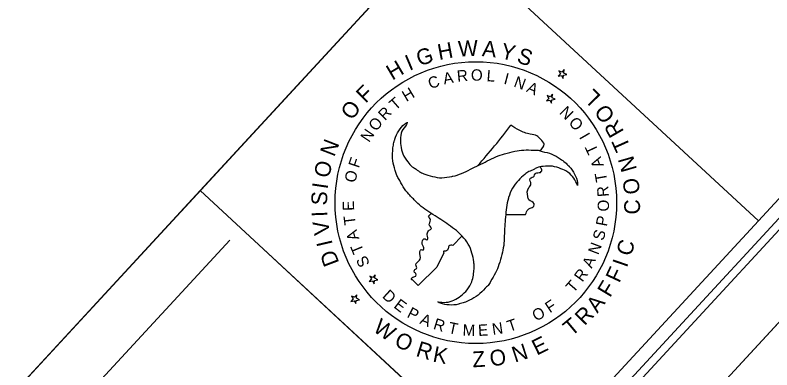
# Model space of a CAD drawing. Extents: x 1767460 to 1770129, y 996106 to 1001438.
# Drawn here: x 1769606.3 to 1769898.5, y 1000271.5 to 1000408.3 of the extents above; entities that cross this region are included whole.
import ezdxf

# ---------------------------------------------------------------- set-up
doc = ezdxf.new("R2010")
doc.units = 0
for name, color, linetype in [('E_NCDOT_Terrain_Model_Contour_Minor', 7, 'Continuous'), ('E_NCDOT_Terrain_Model_Points_Low', 7, 'Continuous'), ('E_NCDOT_Terrain_Model_Triangle_Vertices', 7, 'Continuous'), ('P_NCDOT_Terrain_Points_High', 7, 'Continuous'), ('P_RDY_TL_Draft_DNC_Null_Point', 7, 'Continuous'), ('P_RDY_TL_Grass_Shoulder_Normal', 7, 'Continuous')]:
    doc.layers.add(name, color=color, linetype=linetype)

msp = doc.modelspace()

# ---------------------------------------------------------------- linework, layer by layer
at = {"layer": 'E_NCDOT_Terrain_Model_Contour_Minor'}
msp.add_lwpolyline([(1768744.05, 999038.07), (1770128.77, 1000536.12), (1769152.55, 1001438.49), (1767767.83, 999940.44)], close=True, dxfattribs=at)
at = {"layer": 'E_NCDOT_Terrain_Model_Points_Low'}
msp.add_lwpolyline([(1767804.38, 999935.46), (1769171.05, 1001413.98), (1770107.33, 1000548.53), (1768740.66, 999070.01)], close=True, dxfattribs=at)
at = {"layer": 'E_NCDOT_Terrain_Model_Triangle_Vertices'}
for p, q in [((1769569.13, 1000191.69), (1769689.18, 1000321.56)), ((1769698.57, 1000321.36), (1769799.74, 1000227.84))]:
    msp.add_line(p, q, dxfattribs=at)
for points in [[(1769163.02, 1001400.87), (1767932.52, 1000069.67), (1768864.37, 999208.32), (1770094.87, 1000539.52)], [(1769964.83, 1000651.25), (1769771.23, 1000441.81), (1769893.26, 1000329.01), (1770086.86, 1000538.45)], [(1769677.71, 1000340.64), (1769771.23, 1000441.81), (1769893.26, 1000329.01), (1769799.74, 1000227.84)], [(1769513.61, 1000163.11), (1769677.71, 1000340.64), (1769799.74, 1000227.84), (1769635.64, 1000050.31)]]:
    msp.add_lwpolyline(points, close=True, dxfattribs=at)
at = {"layer": 'P_NCDOT_Terrain_Points_High'}
msp.add_line((1768744.05, 999038.07), (1770128.77, 1000536.12), dxfattribs=at)
msp.add_lwpolyline([(1769163.02, 1001400.87), (1767932.52, 1000069.67), (1768864.37, 999208.32), (1769639.43, 1000046.81), (1769513.61, 1000163.11), (1769964.83, 1000651.25), (1769968.19, 1000656.62)], close=True, dxfattribs=at)
at = {"layer": 'P_RDY_TL_Draft_DNC_Null_Point'}
msp.add_circle((1769784.19, 1000336.02), 54.35, dxfattribs=at)
at = {"layer": 'P_RDY_TL_Grass_Shoulder_Normal'}
for p, q in [((1769816.82, 1000385.73), (1769815.93, 1000384.77)), ((1769815.93, 1000384.77), (1769817.23, 1000385.03)), ((1769817.38, 1000386.34), (1769816.2, 1000386.84)), ((1769816.2, 1000386.84), (1769816.82, 1000385.73)), ((1769817.23, 1000385.03), (1769817.89, 1000383.89)), ((1769818.27, 1000387.3), (1769817.38, 1000386.34)), ((1769817.89, 1000383.89), (1769818.01, 1000385.16)), ((1769818.01, 1000385.16), (1769819.31, 1000385.42)), ((1769818.12, 1000385.99), (1769818.27, 1000387.3)), ((1769819.31, 1000385.42), (1769818.12, 1000385.99)), ((1769812.38, 1000376.22), (1769811.49, 1000375.26)), ((1769812.94, 1000376.83), (1769811.75, 1000377.33)), ((1769811.75, 1000377.33), (1769812.38, 1000376.22)), ((1769813.83, 1000377.79), (1769812.94, 1000376.83)), ((1769813.67, 1000376.48), (1769813.83, 1000377.79)), ((1769814.86, 1000375.91), (1769813.67, 1000376.48)), ((1769811.49, 1000375.26), (1769812.78, 1000375.52)), ((1769812.78, 1000375.52), (1769813.45, 1000374.37)), ((1769813.45, 1000374.37), (1769813.57, 1000375.65)), ((1769813.57, 1000375.65), (1769814.86, 1000375.91)), ((1769795.72, 1000331.45), (1769803.4, 1000331.45)), ((1769775.35, 1000319.42), (1769778.84, 1000323.14)), ((1769771.82, 1000316.6), (1769769.13, 1000311.18)), ((1769769.13, 1000311.18), (1769761.97, 1000303.99)), ((1769743.91, 1000306.58), (1769743.02, 1000305.62)), ((1769744.47, 1000307.19), (1769743.29, 1000307.69)), ((1769743.29, 1000307.69), (1769743.91, 1000306.58)), ((1769745.36, 1000308.15), (1769744.47, 1000307.19)), ((1769744.98, 1000304.74), (1769745.1, 1000306.01)), ((1769745.1, 1000306.01), (1769746.4, 1000306.27)), ((1769745.21, 1000306.84), (1769745.36, 1000308.15)), ((1769746.4, 1000306.27), (1769745.21, 1000306.84)), ((1769761.97, 1000303.99), (1769759.68, 1000306.24)), ((1769743.02, 1000305.62), (1769744.32, 1000305.88)), ((1769744.32, 1000305.88), (1769744.98, 1000304.74)), ((1769738.23, 1000300.46), (1769737.34, 1000299.5)), ((1769738.08, 1000299.15), (1769738.23, 1000300.46)), ((1769738.08, 1000299.15), (1769738.23, 1000300.46)), ((1769736.78, 1000298.89), (1769735.89, 1000297.93)), ((1769735.89, 1000297.93), (1769737.19, 1000298.19)), ((1769737.34, 1000299.5), (1769736.15, 1000300)), ((1769736.15, 1000300), (1769736.78, 1000298.89)), ((1769737.19, 1000298.19), (1769737.85, 1000297.05)), ((1769737.85, 1000297.05), (1769737.97, 1000298.32)), ((1769737.97, 1000298.32), (1769739.27, 1000298.58)), ((1769737.97, 1000298.32), (1769739.26, 1000298.58)), ((1769739.27, 1000298.58), (1769738.08, 1000299.15)), ((1769739.26, 1000298.58), (1769738.08, 1000299.15))]:
    msp.add_line(p, q, dxfattribs=at)
for start, end in [(318.4547, 322.5748), (312.9297, 313.2275)]:
    msp.add_arc((1769573.94, 1000537.1), 281.82, start, end, dxfattribs=at)
for points in [[(1769769.51, 1000297.7), (1769772.72, 1000297.59), (1769775.75, 1000298.38), (1769778.37, 1000300.07), (1769780.82, 1000302.43), (1769782.58, 1000305.53), (1769783.29, 1000308.02), (1769783.38, 1000309.26), (1769783.55, 1000311.4), (1769783.41, 1000313.16), (1769782.68, 1000316.58), (1769781.26, 1000320.02), (1769778.86, 1000323.11), (1769778.64, 1000323.36), (1769775.95, 1000325.8), (1769772.93, 1000327.93), (1769769.98, 1000329.95), (1769766.85, 1000331.96), (1769763.79, 1000334), (1769761.14, 1000336.35), (1769758.32, 1000339.27), (1769756.17, 1000342.06), (1769754.32, 1000345.31), (1769753.5, 1000346.91), (1769753.07, 1000348.45), (1769752.15, 1000352.18), (1769752.11, 1000355.97), (1769752.34, 1000358.23), (1769752.84, 1000360.11), (1769752.92, 1000360.43), (1769754.45, 1000363.7), (1769756.64, 1000366.27), (1769757.63, 1000366.91)], [(1769757.62, 1000367.04), (1769757.63, 1000366.91), (1769755.94, 1000364.23), (1769755.1, 1000361.16), (1769755.24, 1000358.07), (1769756.06, 1000354.79), (1769757.88, 1000351.7), (1769759.65, 1000349.84), (1769760.71, 1000349.17), (1769762.48, 1000347.93), (1769764.05, 1000347.14), (1769767.4, 1000346.12), (1769771.07, 1000345.6), (1769774.97, 1000346.15), (1769775.29, 1000346.21), (1769778.71, 1000347.28), (1769782.12, 1000348.86), (1769785.32, 1000350.41), (1769788.6, 1000352.1), (1769791.94, 1000353.7), (1769795.29, 1000354.84), (1769799.23, 1000355.85), (1769802.69, 1000356.3), (1769806.44, 1000356.29), (1769808.26, 1000356.2), (1769809.81, 1000355.78), (1769813.5, 1000354.75), (1769816.79, 1000352.86), (1769818.65, 1000351.54), (1769820.04, 1000350.17), (1769820.28, 1000349.95), (1769822.32, 1000346.95), (1769823.44, 1000343.76), (1769823.5, 1000342.64)], [(1769808.85, 1000356.07), (1769810.6, 1000358.51), (1769809.17, 1000360.43), (1769807.74, 1000361.8), (1769805.22, 1000362.45), (1769800.89, 1000363.95), (1769797.74, 1000365.83)], [(1769823.5, 1000342.64), (1769822.02, 1000345.43), (1769819.82, 1000347.68), (1769817.03, 1000349.11), (1769813.78, 1000350.03), (1769810.22, 1000350.01), (1769807.72, 1000349.41), (1769806.59, 1000348.81), (1769804.65, 1000347.96), (1769803.16, 1000346.91), (1769800.61, 1000344.58), (1769798.31, 1000341.62), (1769796.85, 1000337.98), (1769796.75, 1000337.68), (1769795.99, 1000334.14), (1769795.63, 1000330.45), (1769795.33, 1000326.88), (1769795.18, 1000323.18), (1769794.94, 1000319.47), (1769794.22, 1000316.02), (1769793.12, 1000312.1), (1769791.77, 1000308.88), (1769789.9, 1000305.66), (1769788.91, 1000304.11), (1769787.78, 1000302.98), (1769785.06, 1000300.33), (1769781.76, 1000298.38), (1769779.71, 1000297.46), (1769777.8, 1000296.97), (1769777.48, 1000296.86), (1769773.89, 1000296.56), (1769770.58, 1000297.19), (1769769.51, 1000297.7)], [(1769803.4, 1000331.45), (1769804.34, 1000333.37), (1769805.97, 1000334.18), (1769806.63, 1000334.69), (1769806.72, 1000335.54), (1769804.7, 1000337.13), (1769804.21, 1000338.37), (1769804.59, 1000341.79), (1769805.47, 1000343.3), (1769805.17, 1000345.29), (1769805.55, 1000345.64), (1769806.4, 1000345.92), (1769807.34, 1000347.43), (1769809.11, 1000347.69), (1769809.62, 1000348.34), (1769809.12, 1000349.7)], [(1769759.68, 1000306.24), (1769759.39, 1000306.37), (1769759.51, 1000307.01), (1769760.98, 1000307.69), (1769761.01, 1000308.68), (1769760.51, 1000309.1), (1769760.45, 1000309.99), (1769761.3, 1000310.6), (1769761.07, 1000312.07), (1769761.47, 1000312.86), (1769762.7, 1000314.19), (1769762.58, 1000317.23), (1769763.09, 1000317.97), (1769763.68, 1000317.75), (1769764.12, 1000318.09), (1769763.47, 1000319.99), (1769763.45, 1000320.33), (1769764.06, 1000322), (1769764.62, 1000322.09), (1769765.29, 1000321.66), (1769765.55, 1000321.74), (1769765.64, 1000322.4), (1769765.45, 1000323.6), (1769765.85, 1000325.09), (1769767.07, 1000326.1), (1769766.3, 1000327.19), (1769766.65, 1000329.37), (1769766.35, 1000330.16), (1769765.87, 1000330.75)], [(1769775.35, 1000319.42), (1769774.5, 1000319.65), (1769773.77, 1000319.21), (1769773.43, 1000317.99), (1769772.85, 1000317.41), (1769771.72, 1000317.2), (1769771.82, 1000316.6)]]:
    msp.add_spline(points, degree=3, dxfattribs=at)

# ---------------------------------------------------------------- texts
at = {"layer": 'P_RDY_TL_Draft_DNC_Null_Point'}
for s, height, rotation, p in [('L', 6.09, 134.6802, (1769832.74, 1000377.05)), ('T', 4.38, 41.0396, (1769753.14, 1000371.35)), ('O', 6.09, 126.2409, (1769838.23, 1000369.48)), ('R', 6.09, 120.0031, (1769841.55, 1000363.41)), ('T', 6.09, 114.1322, (1769844.05, 1000357.4)), ('N', 6.09, 106.1432, (1769846.44, 1000348.87)), ('O', 6.09, 97.7039, (1769847.65, 1000339.6)), ('C', 6.09, 90.3319, (1769847.59, 1000331.43)), ('C', 6.09, 75.2545, (1769844.21, 1000315.09)), ('I', 6.09, 71.0015, (1769842.5, 1000310.7)), ('F', 6.09, 65.0139, (1769839.54, 1000304.76)), ('F', 6.09, 59.0263, (1769835.97, 1000299.15)), ('A', 6.09, 52.0547, (1769831.12, 1000293.14)), ('R', 6.09, 45.8169, (1769826.18, 1000288.3)), ('W', 6.09, 325.4012, (1769744.13, 1000286.67)), ('T', 6.09, 39.946, (1769821.08, 1000284.25)), ('O', 6.09, 334.3659, (1769752.31, 1000281.03)), ('R', 6.09, 342.8053, (1769760.72, 1000276.95)), ('E', 6.09, 26.2029, (1769807.73, 1000276.97)), ('K', 6.09, 349.0431, (1769767.28, 1000274.75)), ('N', 6.09, 18.2139, (1769799.29, 1000274.27)), ('Z', 6.09, 3.42, (1769783.03, 1000272.47)), ('O', 6.09, 9.7745, (1769790.07, 1000272.73))]:
    msp.add_text(s, height=height, rotation=rotation, dxfattribs=at).set_placement(p)
at = {"layer": 'P_RDY_TL_Grass_Shoulder_Normal'}
for s, height, rotation, p in [('H', 6.09, 10.7145, (1769770.01, 1000390.97)), ('W', 6.09, 3.0645, (1769777.48, 1000392.28)), ('A', 6.09, 354.0275, (1769786.43, 1000392.54)), ('Y', 6.09, 346.9996, (1769793.36, 1000391.76)), ('G', 6.09, 18.7679, (1769762.4, 1000388.53)), ('S', 6.09, 340.4761, (1769799.66, 1000390.28)), ('H', 6.09, 30.7052, (1769751.94, 1000383.01)), ('I', 6.09, 23.0553, (1769758.52, 1000386.8)), ('C', 4.38, 20.7273, (1769766.7, 1000379.69)), ('A', 4.38, 10.5711, (1769771.95, 1000381.58)), ('R', 4.38, 5.493, (1769777.08, 1000382.59)), ('O', 4.38, 0.4149, (1769782.3, 1000383.04)), ('L', 4.38, 355.3369, (1769788.2, 1000382.88)), ('I', 4.38, 345.1807, (1769794.69, 1000381.89)), ('N', 4.38, 340.1026, (1769798.52, 1000380.85)), ('A', 4.38, 335.0245, (1769803.43, 1000378.95)), ('F', 6.09, 44.5088, (1769741.58, 1000374.11)), ('H', 4.38, 30.8835, (1769757.36, 1000374.77)), ('O', 6.09, 53.0162, (1769736.37, 1000367.48)), ('N', 4.38, 134.9842, (1769822.26, 1000370.68)), ('R', 4.38, 46.1177, (1769749.14, 1000367.43)), ('O', 4.38, 51.1958, (1769745.72, 1000363.23)), ('O', 4.38, 130.1781, (1769826.06, 1000366.13)), ('N', 4.38, 56.2739, (1769742.96, 1000358.96)), ('I', 4.38, 120.0219, (1769828.51, 1000362.09)), ('N', 6.09, 68.8373, (1769729.51, 1000353.41)), ('T', 4.38, 114.9439, (1769831.66, 1000355.89)), ('F', 4.38, 71.5081, (1769738.98, 1000349.11)), ('A', 4.38, 109.8658, (1769833.68, 1000350.35)), ('O', 6.09, 77.3447, (1769727.49, 1000345.22)), ('O', 4.38, 76.5862, (1769737.61, 1000343.44)), ('T', 4.38, 99.7096, (1769834.94, 1000344.34)), ('I', 6.09, 81.632, (1769726.94, 1000341)), ('R', 4.38, 94.6315, (1769835.59, 1000338.38)), ('S', 6.09, 87.8361, (1769726.7, 1000334.86)), ('E', 4.38, 91.8205, (1769737.23, 1000332.91)), ('O', 4.38, 89.5534, (1769835.59, 1000332.57)), ('I', 6.09, 92.1234, (1769726.93, 1000330.61)), ('T', 4.38, 96.8986, (1769737.83, 1000327.66)), ('P', 4.38, 79.3973, (1769834.75, 1000326.64)), ('V', 6.09, 98.8318, (1769727.92, 1000324.03)), ('A', 4.38, 107.0547, (1769739.26, 1000322.12)), ('S', 4.38, 74.3192, (1769833.41, 1000321.09)), ('I', 6.09, 103.1192, (1769728.95, 1000319.9)), ('N', 4.38, 69.2411, (1769831.45, 1000315.63)), ('T', 4.38, 112.1328, (1769741.04, 1000317.29)), ('D', 6.09, 110.7103, (1769731.52, 1000312.83)), ('S', 4.38, 117.2109, (1769743.41, 1000312.48)), ('A', 4.38, 64.163, (1769828.93, 1000310.43)), ('R', 4.38, 54.0068, (1769825.31, 1000305.13)), ('T', 4.38, 48.9288, (1769821.84, 1000300.95)), ('D', 4.38, 317.5232, (1769747.77, 1000299.65)), ('E', 4.38, 322.6013, (1769752.18, 1000295.76)), ('F', 4.38, 33.6945, (1769812.77, 1000293.27)), ('P', 4.38, 332.7575, (1769757.3, 1000292.03)), ('O', 4.38, 28.6164, (1769807.42, 1000290.11)), ('A', 4.38, 337.8356, (1769762.24, 1000289.44)), ('R', 4.38, 342.9137, (1769767.46, 1000287.37)), ('T', 4.38, 18.4602, (1769797.12, 1000286.12)), ('T', 4.38, 347.9917, (1769773.24, 1000285.78)), ('M', 4.38, 358.1479, (1769779.02, 1000284.74)), ('E', 4.38, 3.226, (1769785.15, 1000284.57)), ('N', 4.38, 8.3041, (1769790.76, 1000285.01))]:
    msp.add_text(s, height=height, rotation=rotation, dxfattribs=at).set_placement(p)

doc.saveas('drawing.dxf')
